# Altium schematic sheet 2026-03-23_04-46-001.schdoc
size 1366 x 383 mm; SheetNumber: 1; SheetTotal: 1
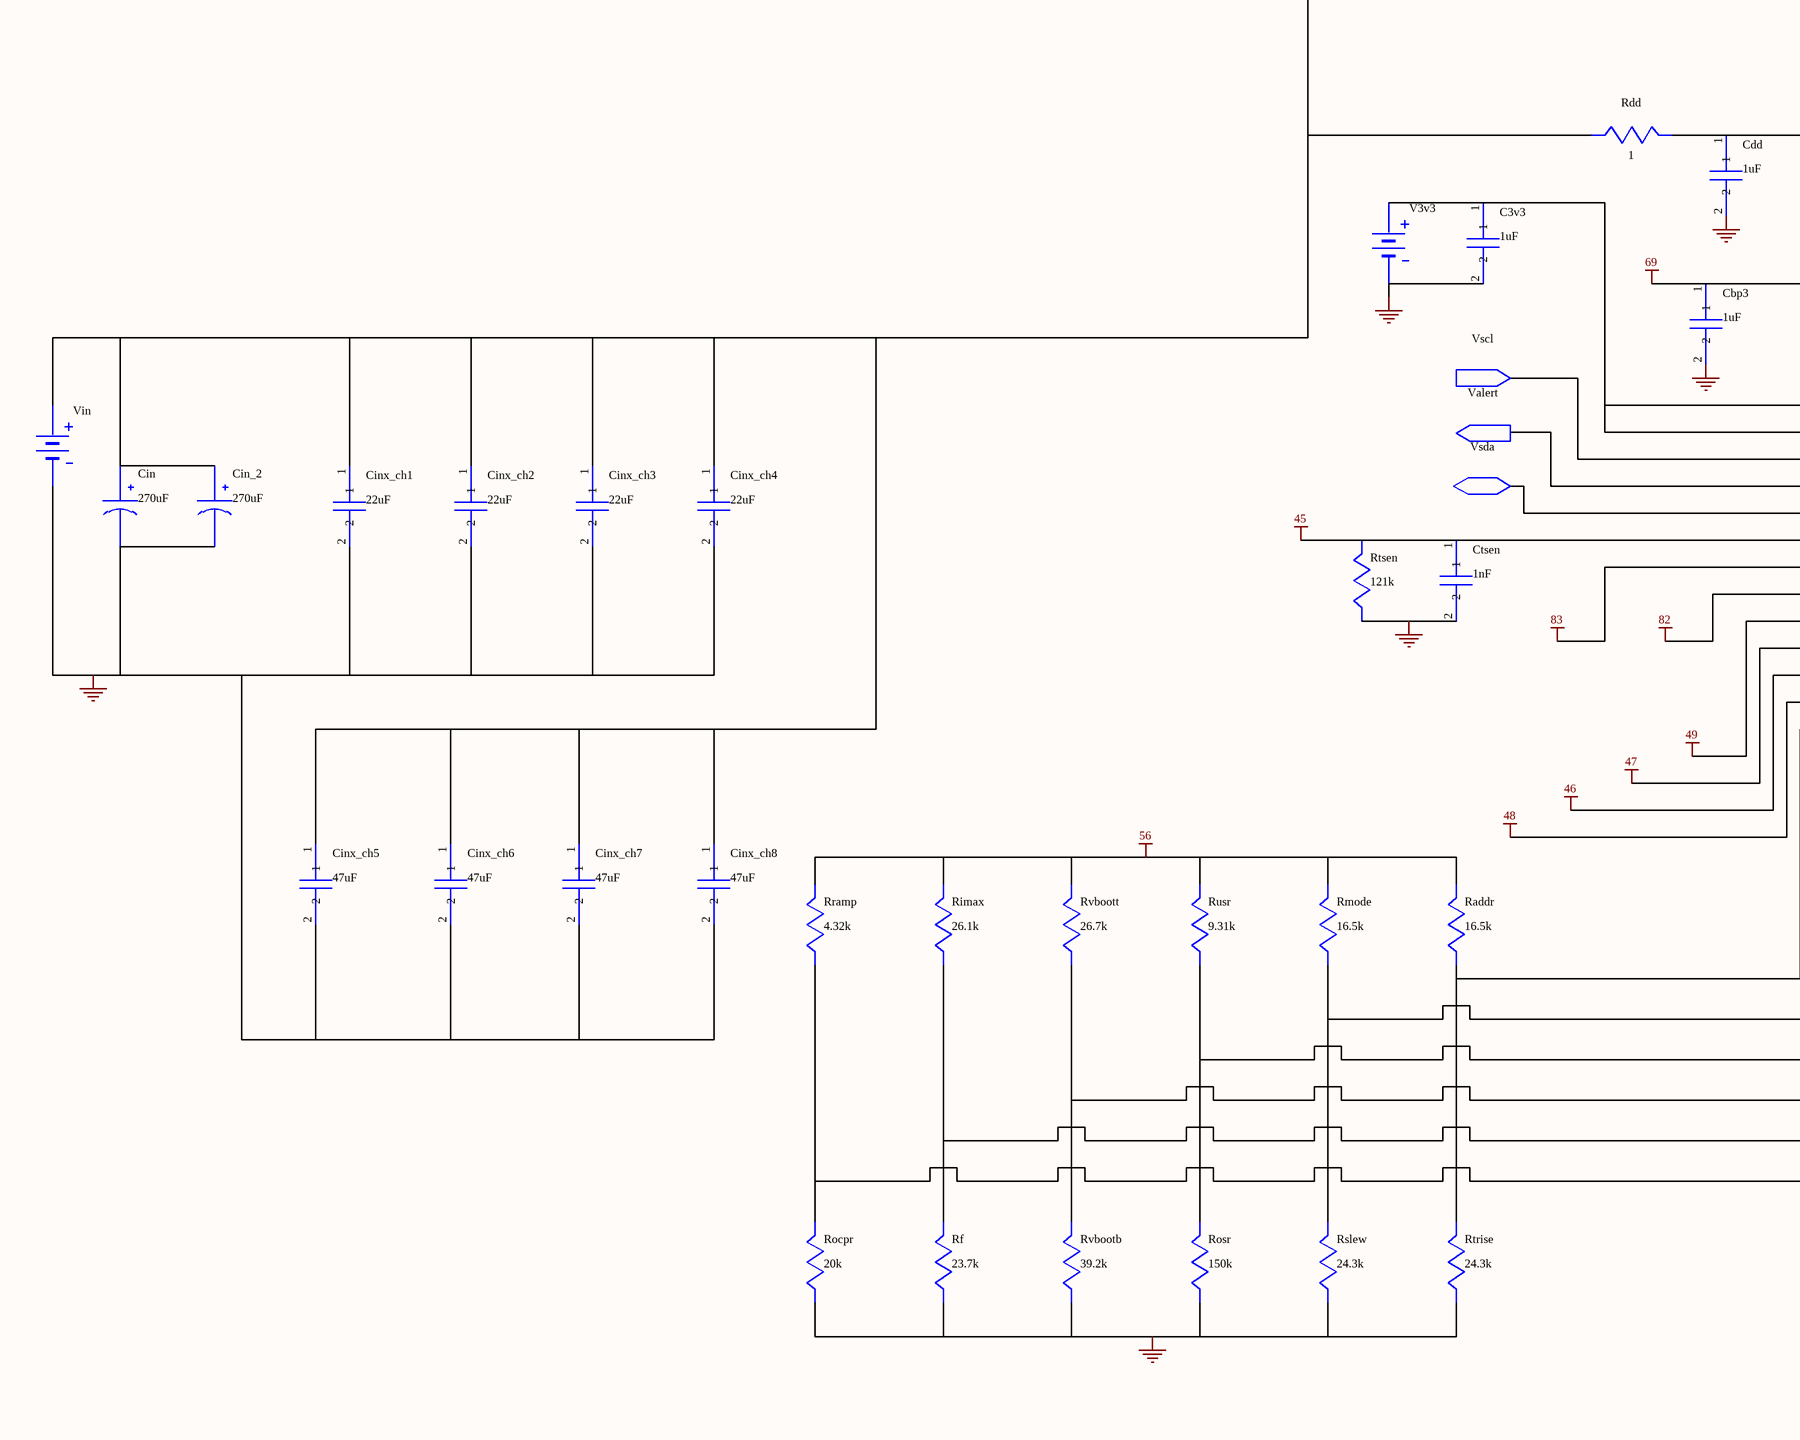
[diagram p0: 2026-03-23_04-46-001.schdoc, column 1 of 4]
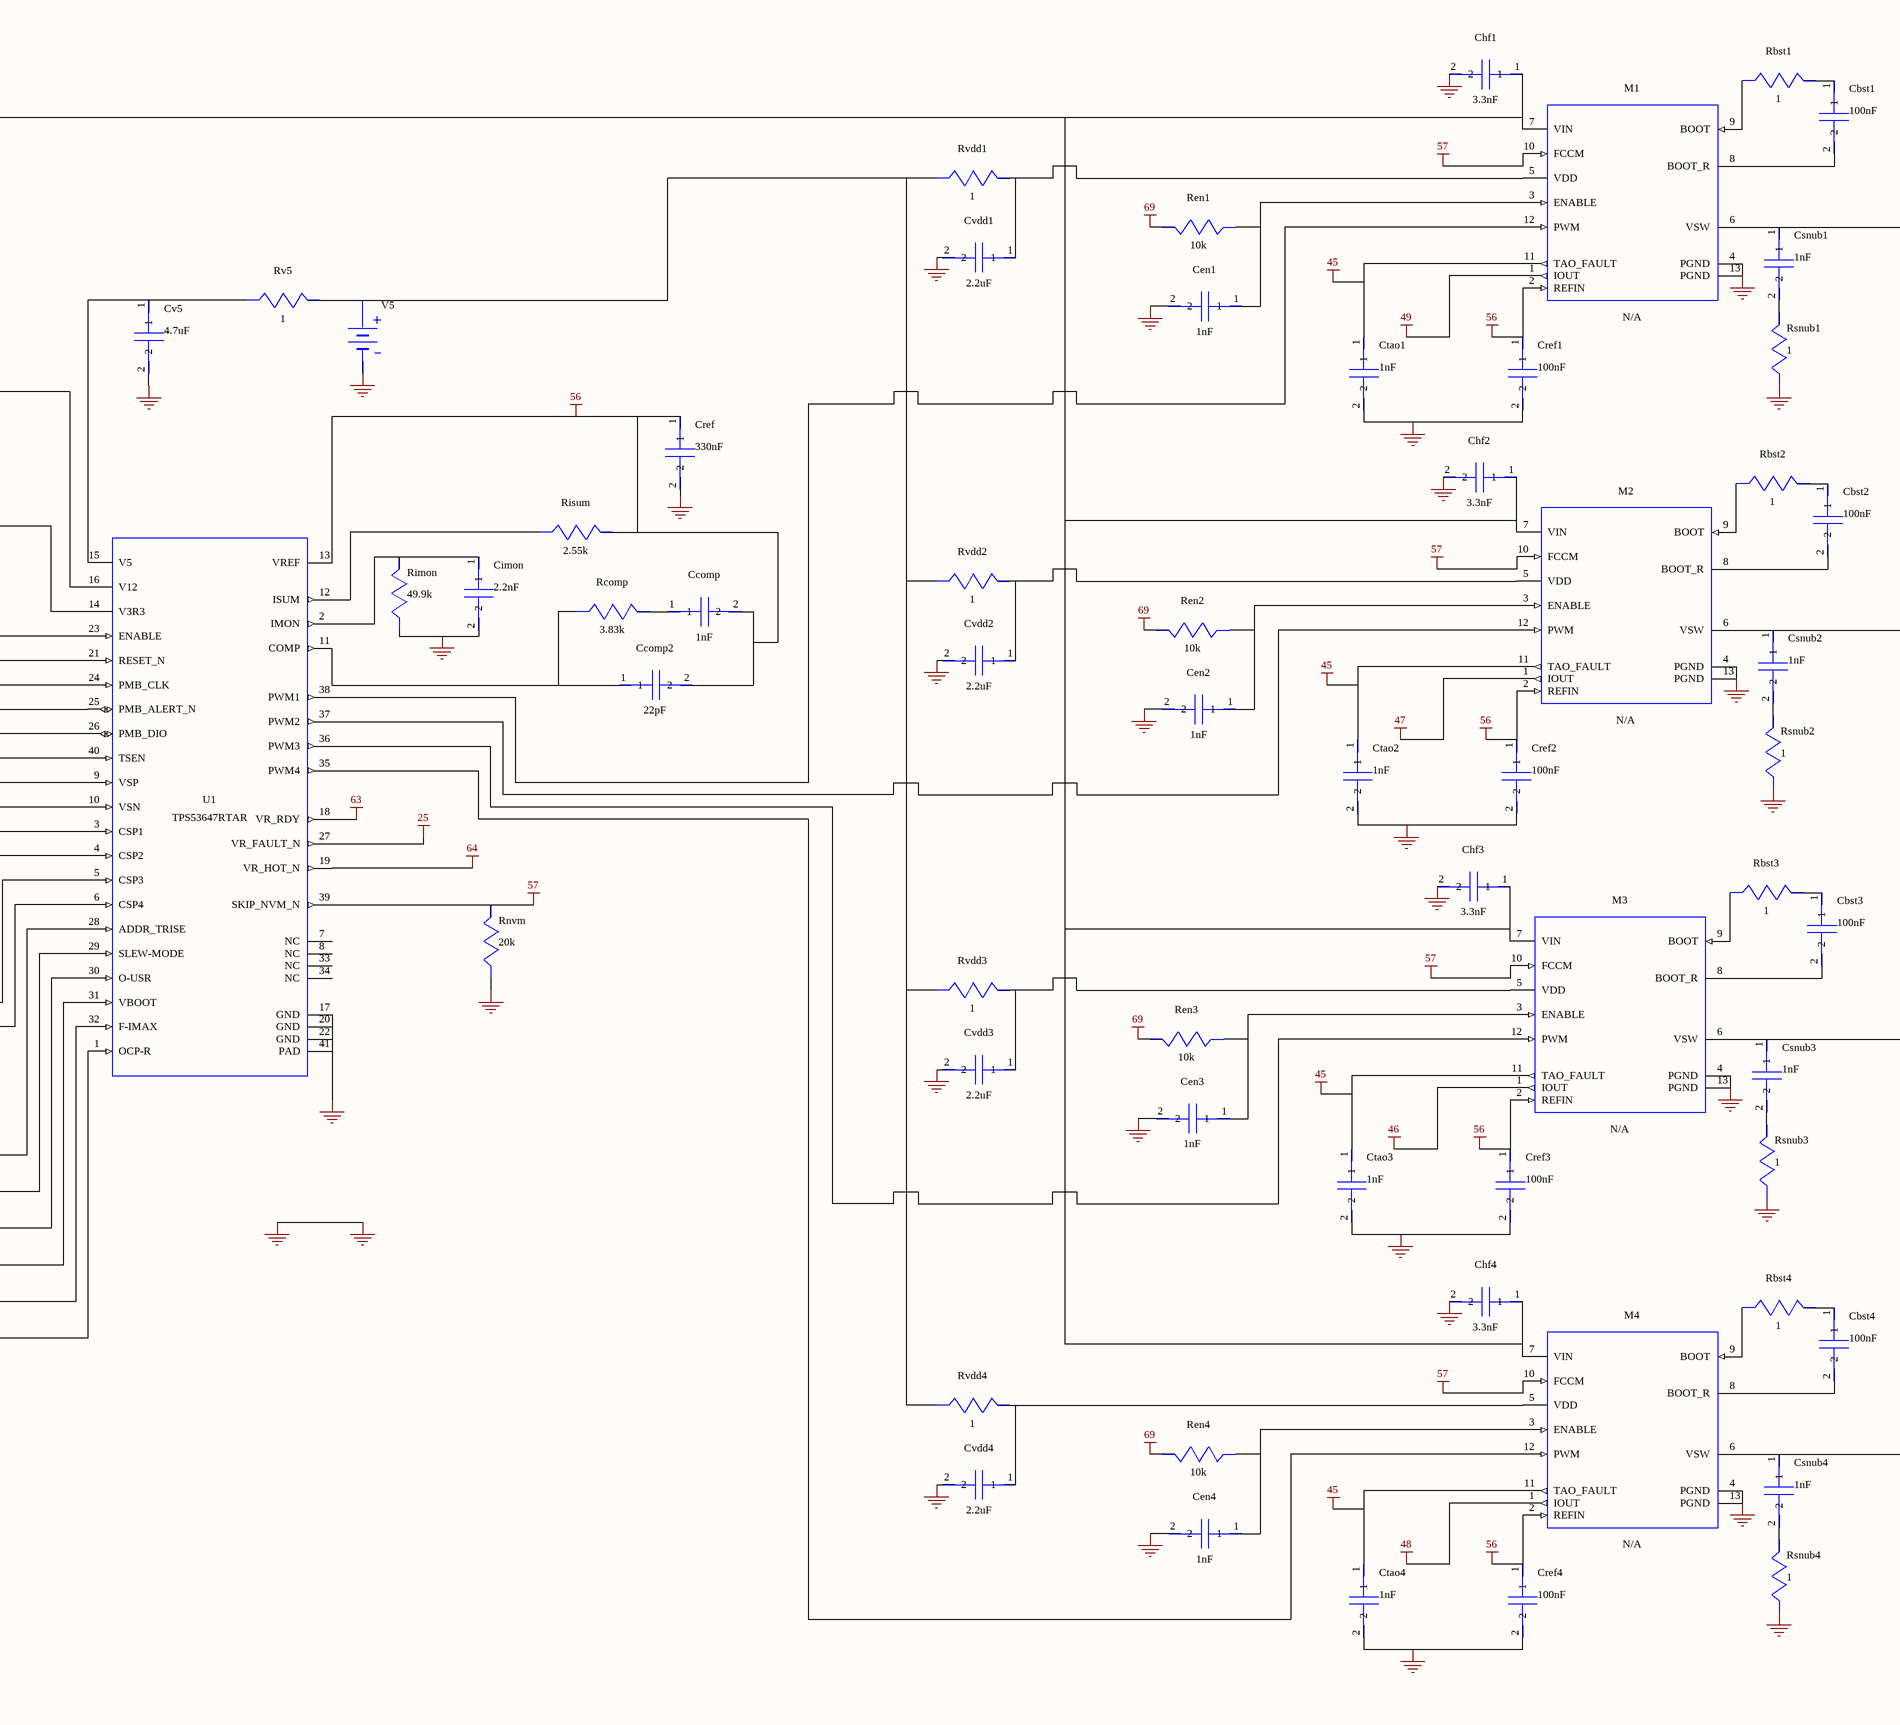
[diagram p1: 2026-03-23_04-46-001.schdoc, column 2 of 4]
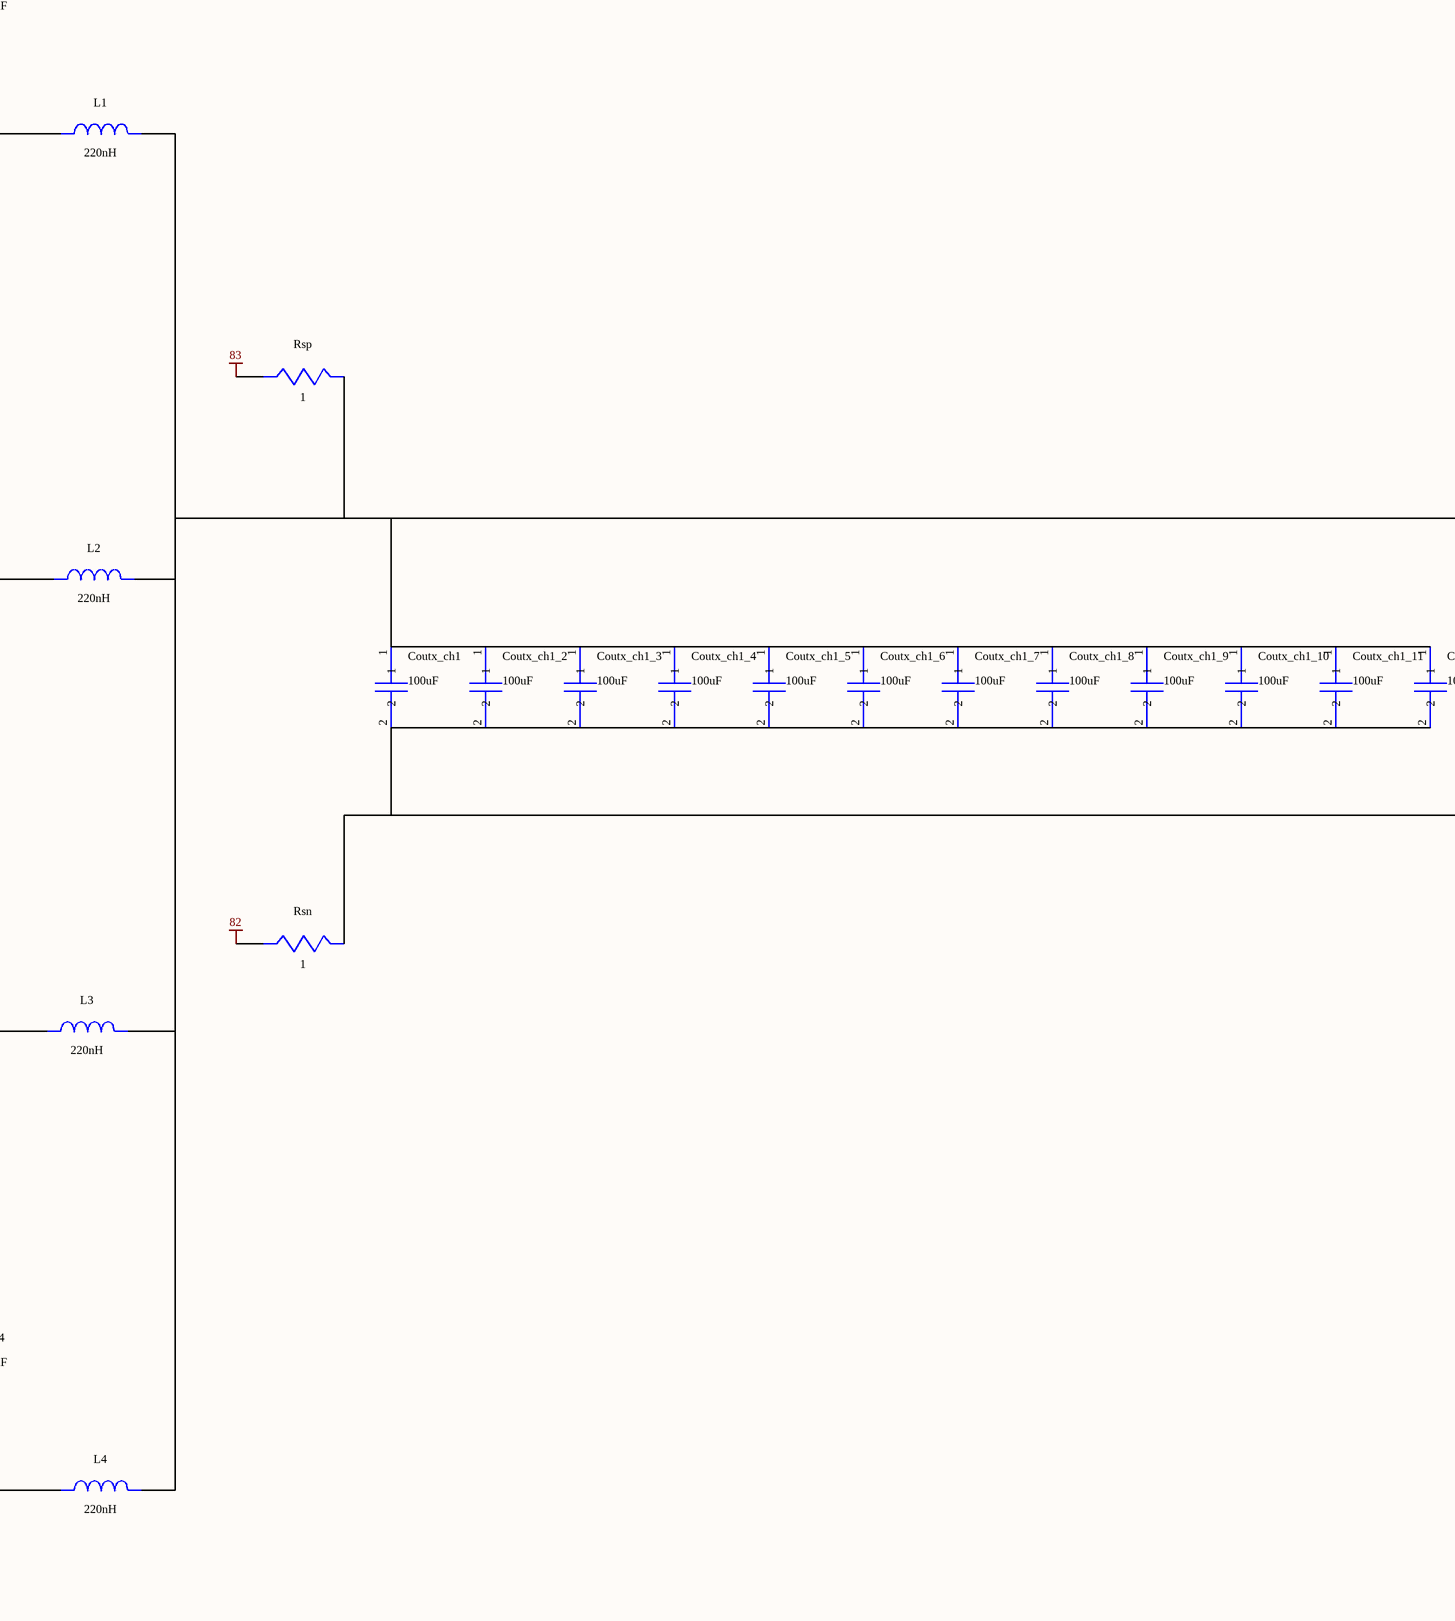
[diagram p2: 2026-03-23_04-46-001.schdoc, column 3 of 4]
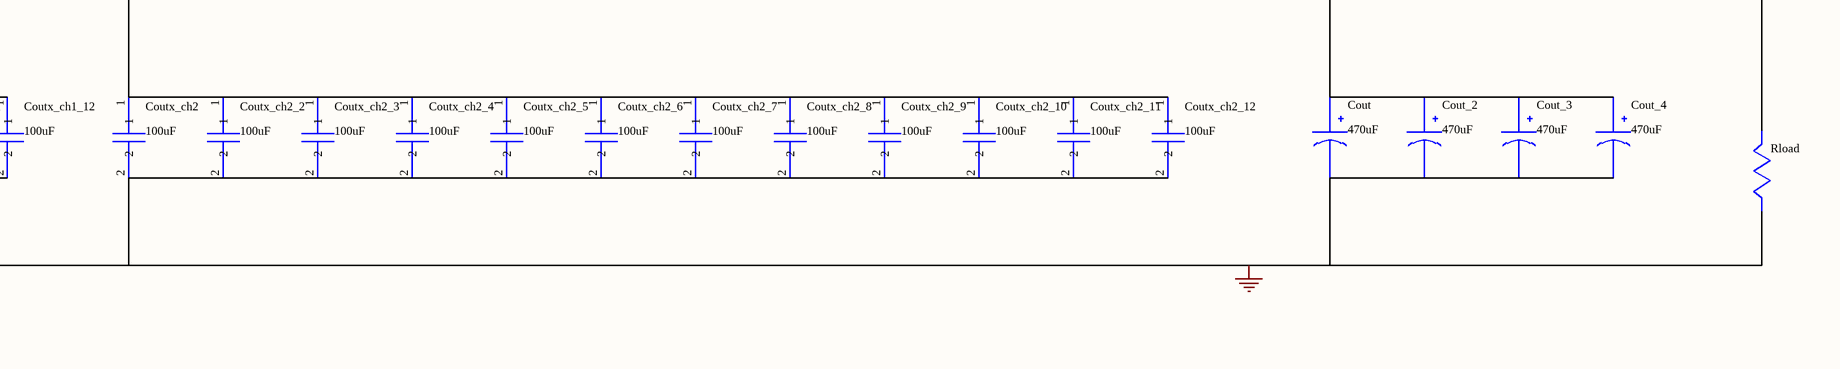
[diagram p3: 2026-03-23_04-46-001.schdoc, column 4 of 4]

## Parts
C3v3  value 1uF  (hidden comment: C0603C105Z8VACTU)
Cbp3  value 1uF  (hidden comment: C0603C105Z8VACTU)
Cbst1  value 100nF  (hidden comment: EMK107B7104KA-T)
Cbst2  value 100nF  (hidden comment: EMK107B7104KA-T)
Cbst3  value 100nF  (hidden comment: EMK107B7104KA-T)
Cbst4  value 100nF  (hidden comment: EMK107B7104KA-T)
Ccomp  value 1nF  (hidden comment: GRM1555C1H102JA01J)
Ccomp2  value 22pF  (hidden comment: CL21C220JBANNNC)
Cdd  value 1uF  (hidden comment: C1608X5R1E105K080AC)
Cen1  value 1nF  (hidden comment: CC0603JRNPO8BN102)
Cen2  value 1nF  (hidden comment: CC0603JRNPO8BN102)
Cen3  value 1nF  (hidden comment: CC0603JRNPO8BN102)
Cen4  value 1nF  (hidden comment: CC0603JRNPO8BN102)
Chf1  value 3.3nF  (hidden comment: CGA1A2X7R1E332K030BA)
Chf2  value 3.3nF  (hidden comment: CGA1A2X7R1E332K030BA)
Chf3  value 3.3nF  (hidden comment: CGA1A2X7R1E332K030BA)
Chf4  value 3.3nF  (hidden comment: CGA1A2X7R1E332K030BA)
Cimon  value 2.2nF  (hidden comment: GRM033R71A222KA01D)
Cin  value 270uF  (hidden comment: 16SVPG270M)
Cin_2  value 270uF  (hidden comment: 16SVPG270M)
Cinx_ch1  value 22uF  (hidden comment: MSASE21GBB5226MTNA01)
Cinx_ch2  value 22uF  (hidden comment: MSASE21GBB5226MTNA01)
Cinx_ch3  value 22uF  (hidden comment: MSASE21GBB5226MTNA01)
Cinx_ch4  value 22uF  (hidden comment: MSASE21GBB5226MTNA01)
Cinx_ch5  value 47uF  (hidden comment: GRM32ER61C476KE15L)
Cinx_ch6  value 47uF  (hidden comment: GRM32ER61C476KE15L)
Cinx_ch7  value 47uF  (hidden comment: GRM32ER61C476KE15L)
Cinx_ch8  value 47uF  (hidden comment: GRM32ER61C476KE15L)
Cout  value 470uF  (hidden comment: EEFGX0D471R)
Cout_2  value 470uF  (hidden comment: EEFGX0D471R)
Cout_3  value 470uF  (hidden comment: EEFGX0D471R)
Cout_4  value 470uF  (hidden comment: EEFGX0D471R)
Coutx_ch1  value 100uF  (hidden comment: GRM32EC80J107ME20L)
Coutx_ch1_2  value 100uF  (hidden comment: GRM32EC80J107ME20L)
Coutx_ch1_3  value 100uF  (hidden comment: GRM32EC80J107ME20L)
Coutx_ch1_4  value 100uF  (hidden comment: GRM32EC80J107ME20L)
Coutx_ch1_5  value 100uF  (hidden comment: GRM32EC80J107ME20L)
Coutx_ch1_6  value 100uF  (hidden comment: GRM32EC80J107ME20L)
Coutx_ch1_7  value 100uF  (hidden comment: GRM32EC80J107ME20L)
Coutx_ch1_8  value 100uF  (hidden comment: GRM32EC80J107ME20L)
Coutx_ch1_9  value 100uF  (hidden comment: GRM32EC80J107ME20L)
Coutx_ch1_10  value 100uF  (hidden comment: GRM32EC80J107ME20L)
Coutx_ch1_11  value 100uF  (hidden comment: GRM32EC80J107ME20L)
Coutx_ch1_12  value 100uF  (hidden comment: GRM32EC80J107ME20L)
Coutx_ch2  value 100uF  (hidden comment: GRM32EC80J107ME20L)
Coutx_ch2_2  value 100uF  (hidden comment: GRM32EC80J107ME20L)
Coutx_ch2_3  value 100uF  (hidden comment: GRM32EC80J107ME20L)
Coutx_ch2_4  value 100uF  (hidden comment: GRM32EC80J107ME20L)
Coutx_ch2_5  value 100uF  (hidden comment: GRM32EC80J107ME20L)
Coutx_ch2_6  value 100uF  (hidden comment: GRM32EC80J107ME20L)
Coutx_ch2_7  value 100uF  (hidden comment: GRM32EC80J107ME20L)
Coutx_ch2_8  value 100uF  (hidden comment: GRM32EC80J107ME20L)
Coutx_ch2_9  value 100uF  (hidden comment: GRM32EC80J107ME20L)
Coutx_ch2_10  value 100uF  (hidden comment: GRM32EC80J107ME20L)
Coutx_ch2_11  value 100uF  (hidden comment: GRM32EC80J107ME20L)
Coutx_ch2_12  value 100uF  (hidden comment: GRM32EC80J107ME20L)
Cref  value 330nF  (hidden comment: C0603C334K8RACTU)
Cref1  value 100nF  (hidden comment: 08053C104KAT2A)
Cref2  value 100nF  (hidden comment: 08053C104KAT2A)
Cref3  value 100nF  (hidden comment: 08053C104KAT2A)
Cref4  value 100nF  (hidden comment: 08053C104KAT2A)
Csnub1  value 1nF  (hidden comment: CC0603JRNPO8BN102)
Csnub2  value 1nF  (hidden comment: CC0603JRNPO8BN102)
Csnub3  value 1nF  (hidden comment: CC0603JRNPO8BN102)
Csnub4  value 1nF  (hidden comment: CC0603JRNPO8BN102)
Ctao1  value 1nF  (hidden comment: GRM033R71C102KA01D)
Ctao2  value 1nF  (hidden comment: GRM033R71C102KA01D)
Ctao3  value 1nF  (hidden comment: GRM033R71C102KA01D)
Ctao4  value 1nF  (hidden comment: GRM033R71C102KA01D)
Ctsen  value 1nF  (hidden comment: GRM033R71C102KA01D)
Cv5  value 4.7uF  (hidden comment: C1608X5R1C475K080AC)
Cvdd1  value 2.2uF  (hidden comment: EMK212BJ225KG-T)
Cvdd2  value 2.2uF  (hidden comment: EMK212BJ225KG-T)
Cvdd3  value 2.2uF  (hidden comment: EMK212BJ225KG-T)
Cvdd4  value 2.2uF  (hidden comment: EMK212BJ225KG-T)
L1  value 220nH  (hidden comment: 7443082022)
L2  value 220nH  (hidden comment: 7443082022)
L3  value 220nH  (hidden comment: 7443082022)
L4  value 220nH  (hidden comment: 7443082022)
M1  CSD95372BQ5M  (value not drawn)
M2  CSD95372BQ5M  (value not drawn)
M3  CSD95372BQ5M  (value not drawn)
M4  CSD95372BQ5M  (value not drawn)
Raddr  value 16.5k  (hidden comment: CRCW040216K5FKED)
Rbst1  value 1  (hidden comment: CRCW04021R00FKED)
Rbst2  value 1  (hidden comment: CRCW04021R00FKED)
Rbst3  value 1  (hidden comment: CRCW04021R00FKED)
Rbst4  value 1  (hidden comment: CRCW04021R00FKED)
Rcomp  value 3.83k  (hidden comment: CRCW04023K83FKED)
Rdd  value 1  (hidden comment: CRCW04021R00FKED)
Ren1  value 10k  (hidden comment: RC0201FR-0710KL)
Ren2  value 10k  (hidden comment: RC0201FR-0710KL)
Ren3  value 10k  (hidden comment: RC0201FR-0710KL)
Ren4  value 10k  (hidden comment: RC0201FR-0710KL)
Rf  value 23.7k  (hidden comment: RC0201FR-0723K7L)
Rimax  value 26.1k  (hidden comment: CRCW040226K1FKED)
Rimon  value 49.9k  (hidden comment: CRCW040249K9FKED)
Risum  value 2.55k  (hidden comment: CRCW04022K55FKED)
Rload  WB_LOAD_RESISTOR  (value not drawn)
Rmode  value 16.5k  (hidden comment: CRCW040216K5FKED)
Rnvm  value 20k  (hidden comment: CRCW040220K0FKED)
Rocpr  value 20k  (hidden comment: CRCW040220K0FKED)
Rosr  value 150k  (hidden comment: CRCW0402150KFKED)
Rramp  value 4.32k  (hidden comment: CRCW04024K32FKED)
Rslew  value 24.3k  (hidden comment: CRCW040224K3FKED)
Rsn  value 1  (hidden comment: CRCW04021R00FKED)
Rsnub1  value 1  (hidden comment: CRCW04021R00FKED)
Rsnub2  value 1  (hidden comment: CRCW04021R00FKED)
Rsnub3  value 1  (hidden comment: CRCW04021R00FKED)
Rsnub4  value 1  (hidden comment: CRCW04021R00FKED)
Rsp  value 1  (hidden comment: CRCW04021R00FKED)
Rtrise  value 24.3k  (hidden comment: CRCW040224K3FKED)
Rtsen  value 121k  (hidden comment: CRCW0402121KFKED)
Rusr  value 9.31k  (hidden comment: CRCW04029K31FKED)
Rv5  value 1  (hidden comment: CRCW04021R00FKED)
Rvbootb  value 39.2k  (hidden comment: CRCW040239K2FKED)
Rvboott  value 26.7k  (hidden comment: CRCW040226K7FKED)
Rvdd1  value 1  (hidden comment: CRCW04021R00FKED)
Rvdd2  value 1  (hidden comment: CRCW04021R00FKED)
Rvdd3  value 1  (hidden comment: CRCW04021R00FKED)
Rvdd4  value 1  (hidden comment: CRCW04021R00FKED)
U1  TPS53647RTAR
V3v3  WB_PRIMITIVE_BATTERY  (value not drawn)
V5  WB_PRIMITIVE_BATTERY  (value not drawn)
Valert  WB_PMBUS_ALERT  (value not drawn)
Vin  WB_BATTERY  (value not drawn)
Vscl  WB_I2C_SCL  (value not drawn)
Vsda  WB_I2C_SDA  (value not drawn)

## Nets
0: C3v3.2 Cbp3.2 Cdd.2 Cen1.2 Cen2.2 Cen3.2 Cen4.2 Chf1.2 Chf2.2 Chf3.2 Chf4.2 Cimon.2 Cin.2(-) Cin_2.2(-) Cinx_ch1.2 Cinx_ch2.2 Cinx_ch3.2 Cinx_ch4.2 Cinx_ch5.2 Cinx_ch6.2 Cinx_ch7.2 Cinx_ch8.2 Cout.2(-) Cout_2.2(-) Cout_3.2(-) Cout_4.2(-) Coutx_ch1.2 Coutx_ch1_2.2 Coutx_ch1_3.2 Coutx_ch1_4.2 Coutx_ch1_5.2 Coutx_ch1_6.2 Coutx_ch1_7.2 Coutx_ch1_8.2 Coutx_ch1_9.2 Coutx_ch1_10.2 Coutx_ch1_11.2 Coutx_ch1_12.2 Coutx_ch2.2 Coutx_ch2_2.2 Coutx_ch2_3.2 Coutx_ch2_4.2 Coutx_ch2_5.2 Coutx_ch2_6.2 Coutx_ch2_7.2 Coutx_ch2_8.2 Coutx_ch2_9.2 Coutx_ch2_10.2 Coutx_ch2_11.2 Coutx_ch2_12.2 Cref.2 Cref1.2 Cref2.2 Cref3.2 Cref4.2 Ctao1.2 Ctao2.2 Ctao3.2 Ctao4.2 Ctsen.2 Cv5.2 Cvdd1.2 Cvdd2.2 Cvdd3.2 Cvdd4.2 M1.4(PGND) M1.13(PGND) M2.4(PGND) M2.13(PGND) M3.4(PGND) M3.13(PGND) M4.4(PGND) M4.13(PGND) Rf.2 Rimon.2 Rload.2 Rnvm.2 Rocpr.2 Rosr.2 Rslew.2 Rsn.1 Rsnub1.2 Rsnub2.2 Rsnub3.2 Rsnub4.2 Rtrise.2 Rtsen.2 Rvbootb.2 U1.17(GND) U1.20(GND) U1.22(GND) U1.41(PAD) V3v3.2(-) V5.2(-) Vin.2(-)
25: U1.27(VR_FAULT_N)
45: Ctao1.1 Ctao2.1 Ctao3.1 Ctao4.1 Ctsen.1 M1.11(TAO_FAULT) M2.11(TAO_FAULT) M3.11(TAO_FAULT) M4.11(TAO_FAULT) Rtsen.1 U1.40(TSEN)
46: M3.1(IOUT) U1.5(CSP3)
47: M2.1(IOUT) U1.4(CSP2)
48: M4.1(IOUT) U1.6(CSP4)
49: M1.1(IOUT) U1.3(CSP1)
56: Ccomp.2 Ccomp2.2 Cref.1 Cref1.1 Cref2.1 Cref3.1 Cref4.1 M1.2(REFIN) M2.2(REFIN) M3.2(REFIN) M4.2(REFIN) Raddr.1 Rimax.1 Risum.1 Rmode.1 Rramp.1 Rusr.1 Rvboott.1 U1.13(VREF)
57: M1.10(FCCM) M2.10(FCCM) M3.10(FCCM) M4.10(FCCM) Rnvm.1 U1.39(SKIP_NVM_N)
63: U1.18(VR_RDY)
64: U1.19(VR_HOT_N)
69: Cbp3.1 Ren1.1 Ren2.1 Ren3.1 Ren4.1 U1.14(V3R3)
82: Rsn.2 U1.10(VSN)
83: Rsp.2 U1.9(VSP)
NetC3v3_1: C3v3.1 U1.21(RESET_N) U1.23(ENABLE) V3v3.1(+)
NetCbst1_1: Cbst1.1 Rbst1.1
NetCbst1_2: Cbst1.2 M1.8(BOOT_R)
NetCbst2_1: Cbst2.1 Rbst2.1
NetCbst2_2: Cbst2.2 M2.8(BOOT_R)
NetCbst3_1: Cbst3.1 Rbst3.1
NetCbst3_2: Cbst3.2 M3.8(BOOT_R)
NetCbst4_1: Cbst4.1 Rbst4.1
NetCbst4_2: Cbst4.2 M4.8(BOOT_R)
NetCcomp2_1: Ccomp2.1 Rcomp.2 U1.11(COMP)
NetCcomp_1: Ccomp.1 Rcomp.1
NetCdd_1: Cdd.1 Rdd.1 U1.16(V12)
NetCen1_1: Cen1.1 M1.3(ENABLE) Ren1.2
NetCen2_1: Cen2.1 M2.3(ENABLE) Ren2.2
NetCen3_1: Cen3.1 M3.3(ENABLE) Ren3.2
NetCen4_1: Cen4.1 M4.3(ENABLE) Ren4.2
NetChf1_1: Chf1.1 Chf2.1 Chf3.1 Chf4.1 Cin.1(+) Cin_2.1(+) Cinx_ch1.1 Cinx_ch2.1 Cinx_ch3.1 Cinx_ch4.1 Cinx_ch5.1 Cinx_ch6.1 Cinx_ch7.1 Cinx_ch8.1 M1.7(VIN) M2.7(VIN) M3.7(VIN) M4.7(VIN) Rdd.2 Vin.1(+)
NetCimon_1: Cimon.1 Rimon.1 U1.2(IMON)
NetCout_1: Cout.1(+) Cout_2.1(+) Cout_3.1(+) Cout_4.1(+) Coutx_ch1.1 Coutx_ch1_2.1 Coutx_ch1_3.1 Coutx_ch1_4.1 Coutx_ch1_5.1 Coutx_ch1_6.1 Coutx_ch1_7.1 Coutx_ch1_8.1 Coutx_ch1_9.1 Coutx_ch1_10.1 Coutx_ch1_11.1 Coutx_ch1_12.1 Coutx_ch2.1 Coutx_ch2_2.1 Coutx_ch2_3.1 Coutx_ch2_4.1 Coutx_ch2_5.1 Coutx_ch2_6.1 Coutx_ch2_7.1 Coutx_ch2_8.1 Coutx_ch2_9.1 Coutx_ch2_10.1 Coutx_ch2_11.1 Coutx_ch2_12.1 L1.1 L2.1 L3.1 L4.1 Rload.1 Rsp.1
NetCsnub1_1: Csnub1.1 L1.2 M1.6(VSW)
NetCsnub1_2: Csnub1.2 Rsnub1.1
NetCsnub2_1: Csnub2.1 L2.2 M2.6(VSW)
NetCsnub2_2: Csnub2.2 Rsnub2.1
NetCsnub3_1: Csnub3.1 L3.2 M3.6(VSW)
NetCsnub3_2: Csnub3.2 Rsnub3.1
NetCsnub4_1: Csnub4.1 L4.2 M4.6(VSW)
NetCsnub4_2: Csnub4.2 Rsnub4.1
NetCv5_1: Cv5.1 Rv5.2 U1.15(V5)
NetCvdd1_1: Cvdd1.1 M1.5(VDD) Rvdd1.1
NetCvdd2_1: Cvdd2.1 M2.5(VDD) Rvdd2.1
NetCvdd3_1: Cvdd3.1 M3.5(VDD) Rvdd3.1
NetCvdd4_1: Cvdd4.1 M4.5(VDD) Rvdd4.1
NetM1_9: M1.9(BOOT) Rbst1.2
NetM1_12: M1.12(PWM) U1.38(PWM1)
NetM2_9: M2.9(BOOT) Rbst2.2
NetM2_12: M2.12(PWM) U1.37(PWM2)
NetM3_9: M3.9(BOOT) Rbst3.2
NetM3_12: M3.12(PWM) U1.36(PWM3)
NetM4_9: M4.9(BOOT) Rbst4.2
NetM4_12: M4.12(PWM) U1.35(PWM4)
NetRaddr_2: Raddr.2 Rtrise.1 U1.28(ADDR_TRISE)
NetRf_1: Rf.1 Rimax.2 U1.32(F-IMAX)
NetRisum_2: Risum.2 U1.12(ISUM)
NetRmode_2: Rmode.2 Rslew.1 U1.29(SLEW-MODE)
NetRocpr_1: Rocpr.1 Rramp.2 U1.1(OCP-R)
NetRosr_1: Rosr.1 Rusr.2 U1.30(O-USR)
NetRv5_1: Rv5.1 Rvdd1.2 Rvdd2.2 Rvdd3.2 Rvdd4.2 V5.1(+)
NetRvbootb_1: Rvbootb.1 Rvboott.2 U1.31(VBOOT)
NetU1_24: U1.24(PMB_CLK) Vscl.1
NetU1_25: U1.25(PMB_ALERT_N) Valert.1
NetU1_26: U1.26(PMB_DIO) Vsda.1

Not connected (* = marked no-connect by the designer): U1 7(NC) 8(NC) 33(NC) 34(NC)

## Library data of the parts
C3v3 Cbp3 = C0603C105Z8VACTU: Manufacturer Name: Kemet
Cbst1-Cbst4 = EMK107B7104KA-T: Manufacturer Name: Taiyo Yuden
Ccomp = GRM1555C1H102JA01J: GRM1555C1H102JA0; Manufacturer Name: MuRata
Ccomp2 = CL21C220JBANNNC: Manufacturer Name: Samsung Electro-Mechanics
Cdd = C1608X5R1E105K080AC: C1608X5R1E105K08; Manufacturer Name: TDK
Cen1-Cen4 Csnub1-Csnub4 = CC0603JRNPO8BN102: CC0603JRNPO8BN10; Manufacturer Name: Yageo
Chf1-Chf4 = CGA1A2X7R1E332K030BA: CGA1A2X7R1E332K0; Manufacturer Name: TDK
Cimon = GRM033R71A222KA01D: GRM033R71A222KA0; Manufacturer Name: MuRata
Cin Cin_2 = 16SVPG270M: Manufacturer Name: Panasonic
Cinx_ch1-Cinx_ch4 = MSASE21GBB5226MTNA01: MSASE21GBB5226MT; Manufacturer Name: Taiyo Yuden
Cinx_ch5-Cinx_ch8 = GRM32ER61C476KE15L: GRM32ER61C476KE1; Manufacturer Name: MuRata
Cout Cout_2-Cout_4 = EEFGX0D471R: Manufacturer Name: Panasonic
Coutx_ch1 Coutx_ch1_2-Coutx_ch1_12 Coutx_ch2 Coutx_ch2_2-Coutx_ch2_12 = GRM32EC80J107ME20L: GRM32EC80J107ME2; Manufacturer Name: MuRata
Cref = C0603C334K8RACTU: Manufacturer Name: Kemet
Cref1-Cref4 = 08053C104KAT2A: Manufacturer Name: AVX
Ctao1-Ctao4 Ctsen = GRM033R71C102KA01D: GRM033R71C102KA0; Manufacturer Name: MuRata
Cv5 = C1608X5R1C475K080AC: C1608X5R1C475K08; Manufacturer Name: TDK
Cvdd1-Cvdd4 = EMK212BJ225KG-T: Manufacturer Name: Taiyo Yuden
L1-L4 = 7443082022: Manufacturer Name: Wurth Elektronik
M1-M4 = CSD95372BQ5M: Manufacturer Name: Texas Instruments
Raddr Rmode = CRCW040216K5FKED: Manufacturer Name: Vishay-Dale
Rbst1-Rbst4 Rdd Rsn Rsnub1-Rsnub4 Rsp Rv5 Rvdd1-Rvdd4 = CRCW04021R00FKED: Manufacturer Name: Vishay-Dale
Rcomp = CRCW04023K83FKED: Manufacturer Name: Vishay-Dale
Ren1-Ren4 = RC0201FR-0710KL: Manufacturer Name: Yageo
Rf = RC0201FR-0723K7L: Manufacturer Name: Yageo
Rimax = CRCW040226K1FKED: Manufacturer Name: Vishay-Dale
Rimon = CRCW040249K9FKED: Manufacturer Name: Vishay-Dale
Risum = CRCW04022K55FKED: Manufacturer Name: Vishay-Dale
Rnvm Rocpr = CRCW040220K0FKED: Manufacturer Name: Vishay-Dale
Rosr = CRCW0402150KFKED: Manufacturer Name: Vishay-Dale
Rramp = CRCW04024K32FKED: Manufacturer Name: Vishay-Dale
Rslew Rtrise = CRCW040224K3FKED: Manufacturer Name: Vishay-Dale
Rtsen = CRCW0402121KFKED: Manufacturer Name: Vishay-Dale
Rusr = CRCW04029K31FKED: Manufacturer Name: Vishay-Dale
Rvbootb = CRCW040239K2FKED: Manufacturer Name: Vishay-Dale
Rvboott = CRCW040226K7FKED: Manufacturer Name: Vishay-Dale
U1 = TPS53647RTAR: Manufacturer Name: Texas Instruments
V3v3 V5 = WB_PRIMITIVE_BATTERY: WB_PRIMITIVE_BAT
